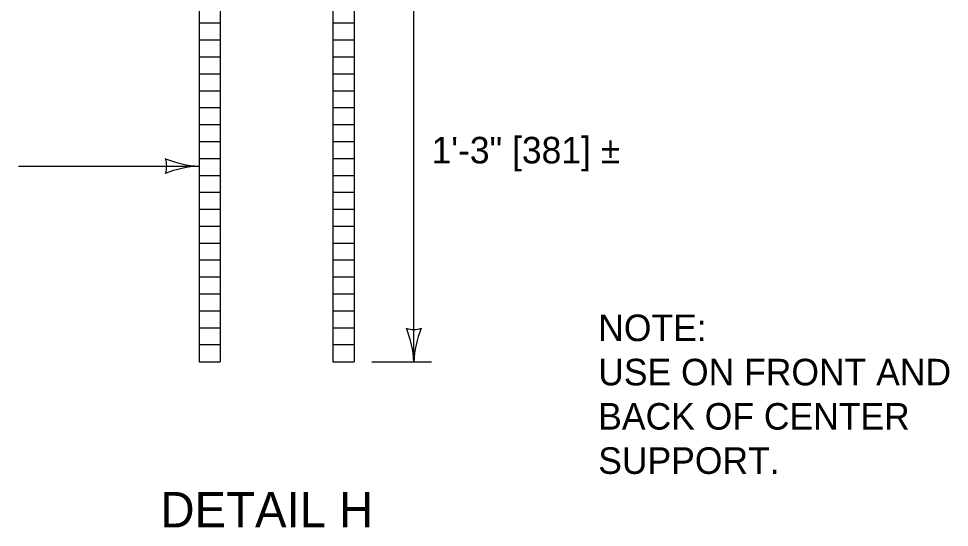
# Model space of a CAD drawing. Extents: x 49991.4 to 50021, y 49987.6 to 50011.4.
# Drawn here: x 50010.682 to 50012.786, y 49991.17 to 49992.32 of the extents above; entities that cross this region are included whole.
import ezdxf

# ---------------------------------------------------------------- set-up
doc = ezdxf.new("R2010")
doc.units = 0
for name, color, linetype in [('Level 1', 7, 'Continuous'), ('Level 2', 7, 'Continuous'), ('Level 3', 7, 'Continuous')]:
    doc.layers.add(name, color=color, linetype=linetype)

msp = doc.modelspace()

# ---------------------------------------------------------------- linework, layer by layer
at = {"layer": 'Level 1'}
for p, q in [((50011.0897, 49993.0741), (50011.0898, 49991.5441)), ((50011.1376, 49993.0741), (50011.1376, 49991.5441)), ((50011.3925, 49993.0741), (50011.3925, 49991.5441)), ((50011.4403, 49993.0741), (50011.4403, 49991.5441)), ((50011.1376, 49992.3091), (50011.0897, 49992.3091)), ((50011.4403, 49992.3091), (50011.3925, 49992.3091)), ((50011.1376, 49992.2708), (50011.0898, 49992.2708)), ((50011.4403, 49992.2708), (50011.3925, 49992.2708)), ((50011.1376, 49992.2326), (50011.0898, 49992.2326)), ((50011.4403, 49992.2326), (50011.3925, 49992.2326)), ((50011.1376, 49992.1943), (50011.0898, 49992.1943)), ((50011.4403, 49992.1943), (50011.3925, 49992.1943)), ((50011.1376, 49992.1561), (50011.0898, 49992.1561)), ((50011.4403, 49992.1561), (50011.3925, 49992.1561)), ((50011.1376, 49992.1178), (50011.0898, 49992.1178)), ((50011.4403, 49992.1178), (50011.3925, 49992.1178)), ((50011.1376, 49992.0796), (50011.0898, 49992.0796)), ((50011.4403, 49992.0796), (50011.3925, 49992.0796)), ((50011.1376, 49992.0413), (50011.0898, 49992.0413)), ((50011.4403, 49992.0413), (50011.3925, 49992.0413)), ((50011.1376, 49992.0031), (50011.0898, 49992.0031)), ((50011.4403, 49992.0031), (50011.3925, 49992.0031)), ((50011.1376, 49991.9648), (50011.0898, 49991.9648)), ((50011.4403, 49991.9648), (50011.3925, 49991.9648)), ((50011.1376, 49991.9266), (50011.0898, 49991.9266)), ((50011.4403, 49991.9266), (50011.3925, 49991.9266)), ((50011.1376, 49991.8883), (50011.0898, 49991.8883)), ((50011.4403, 49991.8883), (50011.3925, 49991.8883)), ((50011.1376, 49991.8501), (50011.0898, 49991.8501)), ((50011.4403, 49991.8501), (50011.3925, 49991.8501)), ((50011.1376, 49991.8118), (50011.0898, 49991.8118)), ((50011.4403, 49991.8118), (50011.3925, 49991.8118)), ((50011.1376, 49991.7736), (50011.0898, 49991.7736)), ((50011.4403, 49991.7736), (50011.3925, 49991.7736)), ((50011.1376, 49991.7353), (50011.0898, 49991.7353)), ((50011.4403, 49991.7353), (50011.3925, 49991.7353)), ((50011.1376, 49991.6971), (50011.0898, 49991.6971)), ((50011.4403, 49991.6971), (50011.3925, 49991.6971)), ((50011.1376, 49991.6588), (50011.0898, 49991.6588)), ((50011.4403, 49991.6588), (50011.3925, 49991.6588)), ((50011.1376, 49991.6206), (50011.0898, 49991.6206)), ((50011.4403, 49991.6206), (50011.3925, 49991.6206)), ((50011.1376, 49991.5823), (50011.0898, 49991.5823)), ((50011.4403, 49991.5823), (50011.3925, 49991.5823)), ((50011.0898, 49991.5441), (50011.1376, 49991.5441)), ((50011.3925, 49991.5441), (50011.4403, 49991.5441))]:
    msp.add_line(p, q, dxfattribs=at)
at = {"layer": 'Level 3'}
for p, q in [((50011.5753, 49991.5441), (50011.5753, 49992.5003)), ((50010.6816, 49991.9865), (50011.0898, 49991.9865)), ((50011.4803, 49991.5441), (50011.6153, 49991.5441))]:
    msp.add_line(p, q, dxfattribs=at)
for centre, radius, start, end in [((50011.0989, 49992.2086), 0.2223, 247.456, 267.6395), ((50010.9616, 49991.9865), 0.0548, 342.1388, 17.8612), ((50011.1013, 49991.7538), 0.233, 92.8273, 112.0772), ((50011.5753, 49991.6723), 0.0548, 252.1388, 287.8612), ((50011.3426, 49991.5326), 0.233, 2.8273, 22.0772), ((50011.7974, 49991.5349), 0.2223, 157.456, 177.6395)]:
    msp.add_arc(centre, radius, start, end, dxfattribs=at)

# ---------------------------------------------------------------- texts
at = {"layer": 'Level 2'}
for s, height, p in [('1\'-3" [381] ±', 0.06, (50011.6153, 49991.9926)), ('NOTE:', 0.06, (50011.9923, 49991.5911)), ('USE ON FRONT AND', 0.06, (50011.9923, 49991.4911)), ('BACK OF CENTER', 0.06, (50011.9923, 49991.3911)), ('SUPPORT.', 0.06, (50011.9923, 49991.2911)), ('DETAIL H', 0.08, (50011.0022, 49991.1703))]:
    msp.add_text(s, height=height, dxfattribs=at).set_placement(p)

doc.saveas('drawing.dxf')
